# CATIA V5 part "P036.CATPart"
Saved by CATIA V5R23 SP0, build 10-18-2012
Part number: P036
Definition: Levier arrière
Bounding box of the stored display mesh (mm): x -27 to -17, y -58.588 to 251.846, z 3.465 to 270.597
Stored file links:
  C:\wamp\www\COURS\CONCEPTION GMP1\TITRE 02-SEMESTRE 2\03-TP7-PRESSE MECANIQUE\eleve\P036.CATPart
  C:\Program Files\Dassault Systemes\B11\intel_a\reffiles\standard\MetricThickPitch.txt
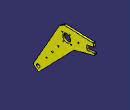
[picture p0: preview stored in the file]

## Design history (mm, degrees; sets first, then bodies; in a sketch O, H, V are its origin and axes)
Set1
  DatumCurve1 to DatumCurve5
  DatumPoint1
  DatumCurve6
  DatumCurve7
  DatumPoint2
  DatumCurve8
  DatumCurve9
Body1 (main body)
  Sketch1 on yz-plane, origin (0, 0, 0), H (0, 1, 0), V (0, 0, 1)
    point P1 (-60.0733, 22.5508)
    line L1 (-60.0733, 22.5508) -> (72.649, 255.4427)
    line L2 (96.2706, 270.5968) -> (245.049, 264.5733)
    point P2 (245.049, 264.5733)
    line L3 (245.049, 264.5733) -> (247.4563, 247.7446)
    point P3 (252.1294, 215.0772)
    line L4 (252.1294, 215.0772) -> (145.9429, 185.2421)
    point P4 (145.9429, 185.2421)
    line L5 (145.9429, 185.2421) -> (-31.8479, 1.3901)
    point P5 (-31.8479, 1.3901)
    line L6 (-31.8479, 1.3901) -> (-60.0733, 22.5508)
    reference projected line E1 (-33.9636, 27.9727) -> (110, 220) from face of DatumCurve1
    reference projected line E2 (110, 220) -> (230, 237.1661) from face of DatumCurve2
    reference projected circle E3 centre (-33.9636, 27.9727) radius 20 from face of DatumCurve3
    reference projected circle E4 centre (-33.9636, 27.9727) radius 20 from face of DatumCurve4
    reference projected circle E5 centre (-33.9636, 27.9727) radius 20 from face of DatumCurve5
    construction circle A1 centre (110, 220) radius 50
    reference projected point E6 (110, 220) from vertex of DatumPoint1
    line L7 (247.4563, 247.7446) -> (209.8392, 242.3635)
    line L8 (209.8392, 242.3635) -> (213.2379, 218.6053)
    line L9 (213.2379, 218.6053) -> (250.8549, 223.9865)
    point P10 (250.8549, 223.9865)
    reference projected line E7 (110, 220) -> (230, 237.1661) from face of DatumCurve6
    reference projected line E8 (110, 220) -> (230, 237.1661) from face of DatumCurve7
    line L10 (250.8549, 223.9865) -> (252.1294, 215.0772)
    reference projected point E9 (110, 220) from vertex of DatumPoint2
    circle A2 centre (-33.9636, 27.9727) radius 8.5
    reference projected circle E10 centre (-33.9636, 27.9727) radius 20 from face of DatumCurve8
    circle A3 centre (110, 220) radius 20
    line L11 (72.649, 255.4427) -> (96.2706, 270.5968)
    radius A1 = 50
    length L8 = 24
    distance L7 E8 = 8
    distance P2 P3 = 50
    distance L3 E9 = 140
    radius A2 = 8.5
    radius A3 = 20
    angle L2 L11 = 145
    length L9 = 38
    symmetry: P5 P1 E1, P2 P3 E2
    tangency: L1 E3, L5 E4, L6 E5, L2 A1, L1 A1, L11 A1
    concentricity: A1 E6, A2 E10
    coincidence: P4 A1, P10 L3, L3 L10
    parallelism: L8 L3, L9 L7, L7 E7
  Pad1: profile Sketch1, direction (-1, 0, 0), length 27, opposite side length -17
  Chamfer1: length 2, angle 45, on edge [face of Pad1 | face of Pad1] (x2)
  Chamfer2: length 3, angle 45, on edge [face of Pad1 | face of Pad1] (x2)
  Fillet1: radius 5, on edge [face of Pad1 | face of Pad1] (x2)
  Chamfer3: length 2, angle 45, on edge [face of Pad1 | face of Pad1] (x2)
  Sketch2 on face of Pad1, origin (-27, 32.0103, 102.9211), H (0, -1, 0), V (0, 0, 1)
    point P1 (23.9845, -18.9404)
    reference projected line E1 (-77.9897, 117.0789) -> (65.9739, -74.9484) from DatumCurve1
    reference projected point E2 (65.9739, -74.9484) from axis of face of Pad1
    distance P1 E2 = 70
    coincidence: P1 E1
  Hole1: placed by Sketch2, at (-27, 8.0258, 83.9807) direction (1, 0, 0), diameter 6, through (limit type 3)
  Sketch3 on face of Pad1, origin (-27, 69.1369, 169.3413), H (0, -1, 0), V (0, 0, 1)
    point P1 (1.1263, -5.3492)
    reference projected line E1 (-40.8631, 50.6587) -> (103.1005, -141.3686) from DatumCurve1
    reference projected point E2 (103.1005, -141.3686) from axis of face of Pad1
    distance P1 E2 = 170
    coincidence: P1 E1
  Hole2: placed by Sketch3, at (-27, 68.0106, 163.992) direction (1, 0, 0), diameter 6, through (limit type 3)
  Sketch4 on face of Pad1, origin (-27, 169.9694, 241.1483), H (0, -1, 0), V (0, 0, 1)
    point P1 (0.5741, -12.6517)
    reference projected point E1 (59.9694, -21.1483) from axis of face of Pad1
    reference projected line E2 (-60.0306, -3.9822) -> (59.9694, -21.1483) from DatumCurve2
    distance P1 E1 = 60
    coincidence: P1 E2
  Hole3: placed by Sketch4, at (-27, 169.3954, 228.4965) direction (1, 0, 0), diameter 6, through (limit type 3)
  Sketch5 on face of Pad1, origin (-27, 121.9478, 249.7561), H (0, -1, 0), V (0, 0, 1)
    point P1 (-4.848, -7.3529)
    reference projected line E1 (11.9478, -29.7561) -> (155.9114, -221.7834) from DatumCurve1
    reference projected point E2 (11.9478, -29.7561) from axis of face of Pad1
    distance P1 E2 = 28
    coincidence: P1 E1
  Hole4: placed by Sketch5, at (-27, 126.7958, 242.4032) direction (1, 0, 0), diameter 6, through (limit type 3)
  CircPattern1: of Hole4, instances 4, angular step 90, axis from face of Pad1
  Sketch6 on face of Pad1, origin (-17, 21.1214, 136.1537), H (0, 1, 0), V (0, 0, 1)
    point P1 (16.8968, -12.1673)
    construction line L1 (63.2624, 49.678) -> (-17.5713, -58.1429)
    construction line L2 (-33.8079, 25.8462) -> (62.9034, -46.6587)
    reference projected point E1 (46.8892, 27.8384) from axis of face of Hole2
    reference projected point E2 (-13.0956, -52.173) from axis of face of Hole1
    reference projected point E3 (46.8892, 27.8384) from axis of face of Hole2
    reference projected point E4 (-13.0956, -52.173) from axis of face of Hole1
    coincidence: E1 L1, L1 E2, P1 L1, P1 L2
    symmetry: E3 E4 L2
  Hole5: placed by Sketch6, at (-17, 38.0182, 123.9864) direction (-1, 0, 0), diameter 8, through (limit type 6)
